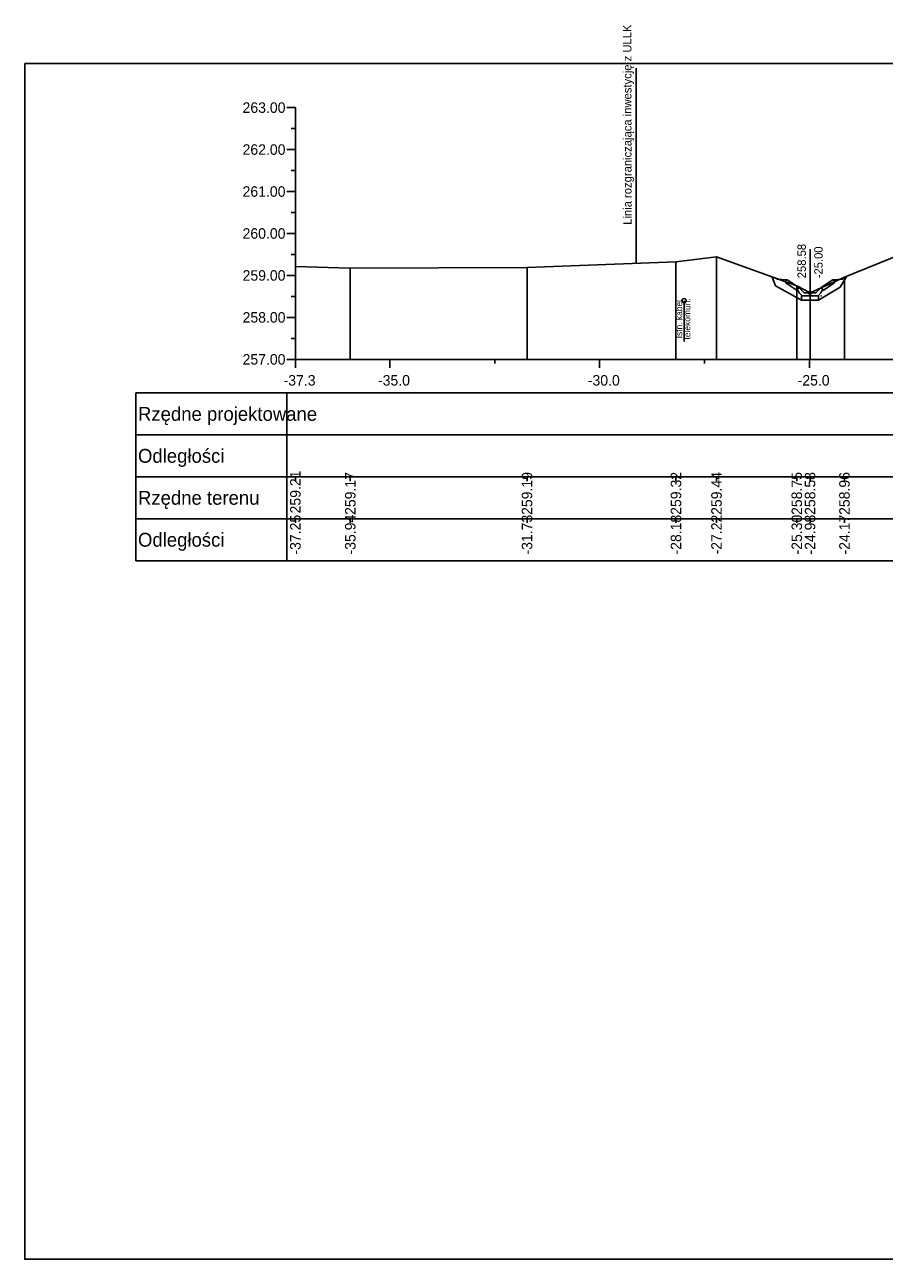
# Model space of a CAD drawing. Extents: x 6516023 to 6560129, y 5513077 to 5529206.
# Drawn here: x 6517179.51 to 6517200, y 5514451.16 to 5514480.58 of the extents above; entities that cross this region are included whole.
import ezdxf

# ---------------------------------------------------------------- set-up
doc = ezdxf.new("R2010")
doc.units = 0
for name, color, linetype in [('TOR_PRZEK_P-kable', 7, 'Continuous'), ('TOR_PRZEK_P-odwodnienie', 7, 'Continuous'), ('TOR_PRZEK_P-tabelka istniejace', 7, 'Continuous'), ('TOR_PRZEK_P-tabelka projektowane', 7, 'Continuous'), ('TOR_PRZEK_P-teren istniejacy', 7, 'Continuous'), ('TOR_PRZEK_P-uklad odniesienia', 7, 'Continuous'), ('TOR_PS_T-granica PKP-projektowana', 7, 'Continuous'), ('TOR_RAMKI-ramka+tabelka 1', 7, 'Continuous')]:
    doc.layers.add(name, color=color, linetype=linetype)

msp = doc.modelspace()

# ---------------------------------------------------------------- linework, layer by layer
at = {"layer": 'TOR_PRZEK_P-kable'}
msp.add_line((6517195.226, 5514474.004), (6517195.226, 5514473.031), dxfattribs=at)
msp.add_circle((6517195.226, 5514474.004), 0.05, dxfattribs=at)
at = {"layer": 'TOR_PRZEK_P-odwodnienie'}
for p, q in [((6517198.228, 5514474.189), (6517198.228, 5514475.233)), ((6517197.919, 5514474.249), (6517197.658, 5514474.423)), ((6517197.964, 5514474.315), (6517197.683, 5514474.502)), ((6517197.93, 5514474.265), (6517197.919, 5514474.249)), ((6517197.921, 5514474.284), (6517197.968, 5514474.308)), ((6517197.964, 5514474.315), (6517197.955, 5514474.303)), ((6517198.088, 5514474.189), (6517197.968, 5514474.308)), ((6517198.368, 5514474.189), (6517198.488, 5514474.308)), ((6517198.488, 5514474.308), (6517198.536, 5514474.284)), ((6517198.493, 5514474.315), (6517198.773, 5514474.502)), ((6517198.493, 5514474.315), (6517198.501, 5514474.303)), ((6517198.526, 5514474.265), (6517198.537, 5514474.249)), ((6517198.537, 5514474.249), (6517198.798, 5514474.423)), ((6517198.038, 5514474.119), (6517198.418, 5514474.119)), ((6517198.088, 5514474.189), (6517198.368, 5514474.189))]:
    msp.add_line(p, q, dxfattribs=at)
for points in [[(6517197.327, 5514474.568), (6517197.403, 5514474.361), (6517198.028, 5514474.019)], [(6517197.437, 5514474.514), (6517197.683, 5514474.502)], [(6517198.428, 5514474.019), (6517198.949, 5514474.329), (6517199.103, 5514474.587)], [(6517199.02, 5514474.514), (6517198.773, 5514474.502)], [(6517197.633, 5514474.475), (6517197.683, 5514474.502)], [(6517197.633, 5514474.475), (6517197.658, 5514474.423)], [(6517197.955, 5514474.303), (6517197.92, 5514474.284)], [(6517197.92, 5514474.284), (6517197.93, 5514474.265)], [(6517197.968, 5514474.189), (6517197.921, 5514474.284)], [(6517198.488, 5514474.189), (6517198.536, 5514474.284)], [(6517198.501, 5514474.303), (6517198.536, 5514474.284)], [(6517198.536, 5514474.284), (6517198.526, 5514474.265)], [(6517198.823, 5514474.475), (6517198.773, 5514474.502)], [(6517198.823, 5514474.475), (6517198.798, 5514474.423)], [(6517198.038, 5514474.119), (6517197.968, 5514474.189)], [(6517198.028, 5514474.119), (6517198.027, 5514474.12), (6517198.028, 5514474.119), (6517198.027, 5514474.119), (6517198.028, 5514474.119), (6517198.028, 5514474.119), (6517198.028, 5514474.119), (6517198.028, 5514474.12)], [(6517198.028, 5514474.119), (6517198.028, 5514474.12), (6517198.028, 5514474.119), (6517198.028, 5514474.119), (6517198.028, 5514474.119), (6517198.029, 5514474.119), (6517198.028, 5514474.119), (6517198.029, 5514474.12)], [(6517198.428, 5514474.119), (6517198.028, 5514474.119), (6517198.028, 5514474.019), (6517198.428, 5514474.019), (6517198.428, 5514474.119)], [(6517198.418, 5514474.119), (6517198.488, 5514474.189)], [(6517198.428, 5514474.119), (6517198.427, 5514474.12), (6517198.428, 5514474.119), (6517198.427, 5514474.119), (6517198.428, 5514474.119), (6517198.428, 5514474.119), (6517198.428, 5514474.119), (6517198.428, 5514474.12)], [(6517198.428, 5514474.119), (6517198.428, 5514474.12), (6517198.428, 5514474.119), (6517198.428, 5514474.119), (6517198.428, 5514474.119), (6517198.429, 5514474.119), (6517198.428, 5514474.119), (6517198.429, 5514474.12)], [(6517198.492, 5514474.12), (6517198.491, 5514474.12), (6517198.492, 5514474.12), (6517198.491, 5514474.119), (6517198.492, 5514474.12), (6517198.492, 5514474.119), (6517198.492, 5514474.12), (6517198.492, 5514474.12)], [(6517198.492, 5514474.12), (6517198.492, 5514474.12), (6517198.492, 5514474.12), (6517198.492, 5514474.119), (6517198.492, 5514474.12), (6517198.493, 5514474.119), (6517198.492, 5514474.12), (6517198.493, 5514474.12)]]:
    msp.add_lwpolyline(points, dxfattribs=at)
msp.add_circle((6517198.228, 5514474.189), 0.035, dxfattribs=at)
at = {"layer": 'TOR_PRZEK_P-tabelka istniejace'}
for p, q in [((6517182.163, 5514469.806), (6517182.163, 5514467.806)), ((6517185.763, 5514469.806), (6517185.763, 5514467.806)), ((6517185.963, 5514469.706), (6517185.963, 5514469.806)), ((6517187.272, 5514469.706), (6517187.272, 5514469.806)), ((6517191.483, 5514469.706), (6517191.483, 5514469.806)), ((6517195.033, 5514469.706), (6517195.033, 5514469.806)), ((6517195.998, 5514469.706), (6517195.998, 5514469.806)), ((6517197.912, 5514469.706), (6517197.912, 5514469.806)), ((6517198.228, 5514469.706), (6517198.228, 5514469.806)), ((6517199.048, 5514469.706), (6517199.048, 5514469.806)), ((6517182.163, 5514468.806), (6517265.963, 5514468.806)), ((6517185.963, 5514468.706), (6517185.963, 5514468.806)), ((6517187.272, 5514468.706), (6517187.272, 5514468.806)), ((6517191.483, 5514468.706), (6517191.483, 5514468.806)), ((6517195.033, 5514468.706), (6517195.033, 5514468.806)), ((6517195.998, 5514468.706), (6517195.998, 5514468.806)), ((6517197.912, 5514468.706), (6517197.912, 5514468.806)), ((6517198.228, 5514468.706), (6517198.228, 5514468.806)), ((6517199.048, 5514468.706), (6517199.048, 5514468.806))]:
    msp.add_line(p, q, dxfattribs=at)
for points in [[(6517185.963, 5514474.818), (6517185.963, 5514472.806), (6517185.963, 5514472.676), (6517185.963, 5514472.606)], [(6517195.033, 5514474.927), (6517195.033, 5514472.806), (6517195.033, 5514472.676), (6517195.033, 5514472.606)], [(6517195.998, 5514475.05), (6517195.998, 5514472.806), (6517195.998, 5514472.676), (6517195.998, 5514472.606)], [(6517187.272, 5514474.776), (6517187.272, 5514472.806), (6517187.272, 5514472.676), (6517187.272, 5514472.606)], [(6517191.483, 5514474.794), (6517191.483, 5514472.806), (6517191.483, 5514472.676), (6517191.483, 5514472.606)], [(6517199.048, 5514474.564), (6517199.048, 5514472.806), (6517199.048, 5514472.676), (6517199.048, 5514472.606)], [(6517197.912, 5514474.355), (6517197.912, 5514472.806), (6517197.912, 5514472.676), (6517197.912, 5514472.606)], [(6517198.228, 5514474.189), (6517198.228, 5514472.806), (6517198.228, 5514472.676), (6517198.228, 5514472.606)]]:
    msp.add_lwpolyline(points, dxfattribs=at)
msp.add_lwpolyline([(6517182.163, 5514469.806), (6517182.163, 5514467.806), (6517265.963, 5514467.806), (6517265.963, 5514469.806)], close=True, dxfattribs=at)
at = {"layer": 'TOR_PRZEK_P-tabelka projektowane'}
for p, q in [((6517182.163, 5514471.806), (6517182.163, 5514469.806)), ((6517185.763, 5514471.806), (6517185.763, 5514469.806)), ((6517182.163, 5514470.806), (6517265.963, 5514470.806))]:
    msp.add_line(p, q, dxfattribs=at)
msp.add_lwpolyline([(6517182.163, 5514471.806), (6517182.163, 5514469.806), (6517265.963, 5514469.806), (6517265.963, 5514471.806)], close=True, dxfattribs=at)
at = {"layer": 'TOR_PRZEK_P-teren istniejacy'}
msp.add_lwpolyline([(6517185.963, 5514474.818), (6517187.272, 5514474.776), (6517191.483, 5514474.794), (6517195.033, 5514474.927), (6517195.998, 5514475.05), (6517197.912, 5514474.355), (6517198.228, 5514474.189), (6517199.048, 5514474.564), (6517202.635, 5514476.018)], dxfattribs=at)
at = {"layer": 'TOR_PRZEK_P-uklad odniesienia'}
for p, q in [((6517185.763, 5514478.606), (6517185.963, 5514478.606)), ((6517185.963, 5514478.606), (6517185.963, 5514472.606)), ((6517185.863, 5514478.106), (6517185.963, 5514478.106)), ((6517185.763, 5514477.606), (6517185.963, 5514477.606)), ((6517185.863, 5514477.106), (6517185.963, 5514477.106)), ((6517185.763, 5514476.606), (6517185.963, 5514476.606)), ((6517185.863, 5514476.106), (6517185.963, 5514476.106)), ((6517185.763, 5514475.606), (6517185.963, 5514475.606)), ((6517185.863, 5514475.106), (6517185.963, 5514475.106)), ((6517185.763, 5514474.606), (6517185.963, 5514474.606)), ((6517185.863, 5514474.106), (6517185.963, 5514474.106)), ((6517185.763, 5514473.606), (6517185.963, 5514473.606)), ((6517185.863, 5514473.106), (6517185.963, 5514473.106)), ((6517185.763, 5514472.606), (6517185.963, 5514472.606)), ((6517185.963, 5514472.606), (6517265.963, 5514472.606)), ((6517185.963, 5514472.506), (6517185.963, 5514472.606)), ((6517185.963, 5514472.406), (6517185.963, 5514472.606)), ((6517188.213, 5514472.406), (6517188.213, 5514472.606)), ((6517190.713, 5514472.506), (6517190.713, 5514472.606)), ((6517193.213, 5514472.406), (6517193.213, 5514472.606)), ((6517195.713, 5514472.506), (6517195.713, 5514472.606)), ((6517198.213, 5514472.406), (6517198.213, 5514472.606))]:
    msp.add_line(p, q, dxfattribs=at)
at = {"layer": 'TOR_PS_T-granica PKP-projektowana'}
msp.add_line((6517194.085, 5514474.892), (6517194.085, 5514479.549), dxfattribs=at)
at = {"layer": 'TOR_RAMKI-ramka+tabelka 1'}
msp.add_lwpolyline([(6517179.513, 5514479.656), (6517427.013, 5514479.656), (6517427.013, 5514451.156), (6517179.513, 5514451.156)], close=True, dxfattribs=at)

# ---------------------------------------------------------------- texts
at = {"layer": 'TOR_PRZEK_P-kable'}
for s, height, p in [('Istn. kabel', 0.14999, (6517195.182, 5514473.107)), ('telekomun.', 0.15, (6517195.376, 5514473.079))]:
    msp.add_text(s, height=height, rotation=90.0511, dxfattribs=at).set_placement(p)
at = {"layer": 'TOR_PRZEK_P-odwodnienie'}
for s, p in [('258.58', (6517198.128, 5514474.539)), ('-25.00', (6517198.528, 5514474.539))]:
    msp.add_text(s, height=0.2, rotation=90, dxfattribs=at).set_placement(p)
at = {"layer": 'TOR_PRZEK_P-tabelka istniejace'}
for s, p in [('259.21', (6517186.088, 5514468.933)), ('259.17', (6517187.397, 5514468.898)), ('259.19', (6517191.608, 5514468.898)), ('259.32', (6517195.158, 5514468.9)), ('259.44', (6517196.123, 5514468.899)), ('258.75', (6517198.037, 5514468.897)), ('258.58', (6517198.353, 5514468.898)), ('258.96', (6517199.173, 5514468.898)), ('-37.25', (6517186.088, 5514467.953)), ('-35.94', (6517187.397, 5514467.955)), ('-31.73', (6517191.608, 5514467.954)), ('-28.18', (6517195.158, 5514467.954)), ('-27.22', (6517196.123, 5514467.956)), ('-25.30', (6517198.037, 5514467.955)), ('-24.98', (6517198.353, 5514467.954)), ('-24.17', (6517199.173, 5514467.955))]:
    msp.add_text(s, height=0.25, rotation=90, dxfattribs=at).set_placement(p)
for s, p in [('Rzędne terenu', (6517182.213, 5514469.141)), ('Odległości', (6517182.213, 5514468.141))]:
    msp.add_text(s, height=0.33, dxfattribs=at).set_placement(p)
at = {"layer": 'TOR_PRZEK_P-tabelka projektowane'}
for s, p in [('Rzędne projektowane', (6517182.213, 5514471.141)), ('Odległości', (6517182.213, 5514470.141))]:
    msp.add_text(s, height=0.33, dxfattribs=at).set_placement(p)
at = {"layer": 'TOR_PRZEK_P-uklad odniesienia'}
for s, height, p in [('263.00', 0.25, (6517184.705, 5514478.481)), ('262.00', 0.25, (6517184.705, 5514477.481)), ('261.00', 0.25, (6517184.705, 5514476.481)), ('260.00', 0.25, (6517184.705, 5514475.481)), ('259.00', 0.25, (6517184.705, 5514474.481)), ('258.00', 0.25, (6517184.705, 5514473.481)), ('257.00', 0.25, (6517184.705, 5514472.481)), ('-', 0.0001, (6517185.963, 5514472.606)), ('-37.3', 0.25, (6517185.682, 5514471.981)), ('-35.0', 0.25, (6517187.932, 5514471.981)), ('-30.0', 0.25, (6517192.932, 5514471.981)), ('-25.0', 0.25, (6517197.932, 5514471.981))]:
    msp.add_text(s, height=height, dxfattribs=at).set_placement(p)
at = {"layer": 'TOR_PS_T-granica PKP-projektowana'}
msp.add_text('Linia rozgraniczająca inwestycję z ULLK', height=0.2, rotation=90.0511, dxfattribs=at).set_placement((6517193.975, 5514475.813))

doc.saveas('drawing.dxf')
